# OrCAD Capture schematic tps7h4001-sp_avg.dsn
size B
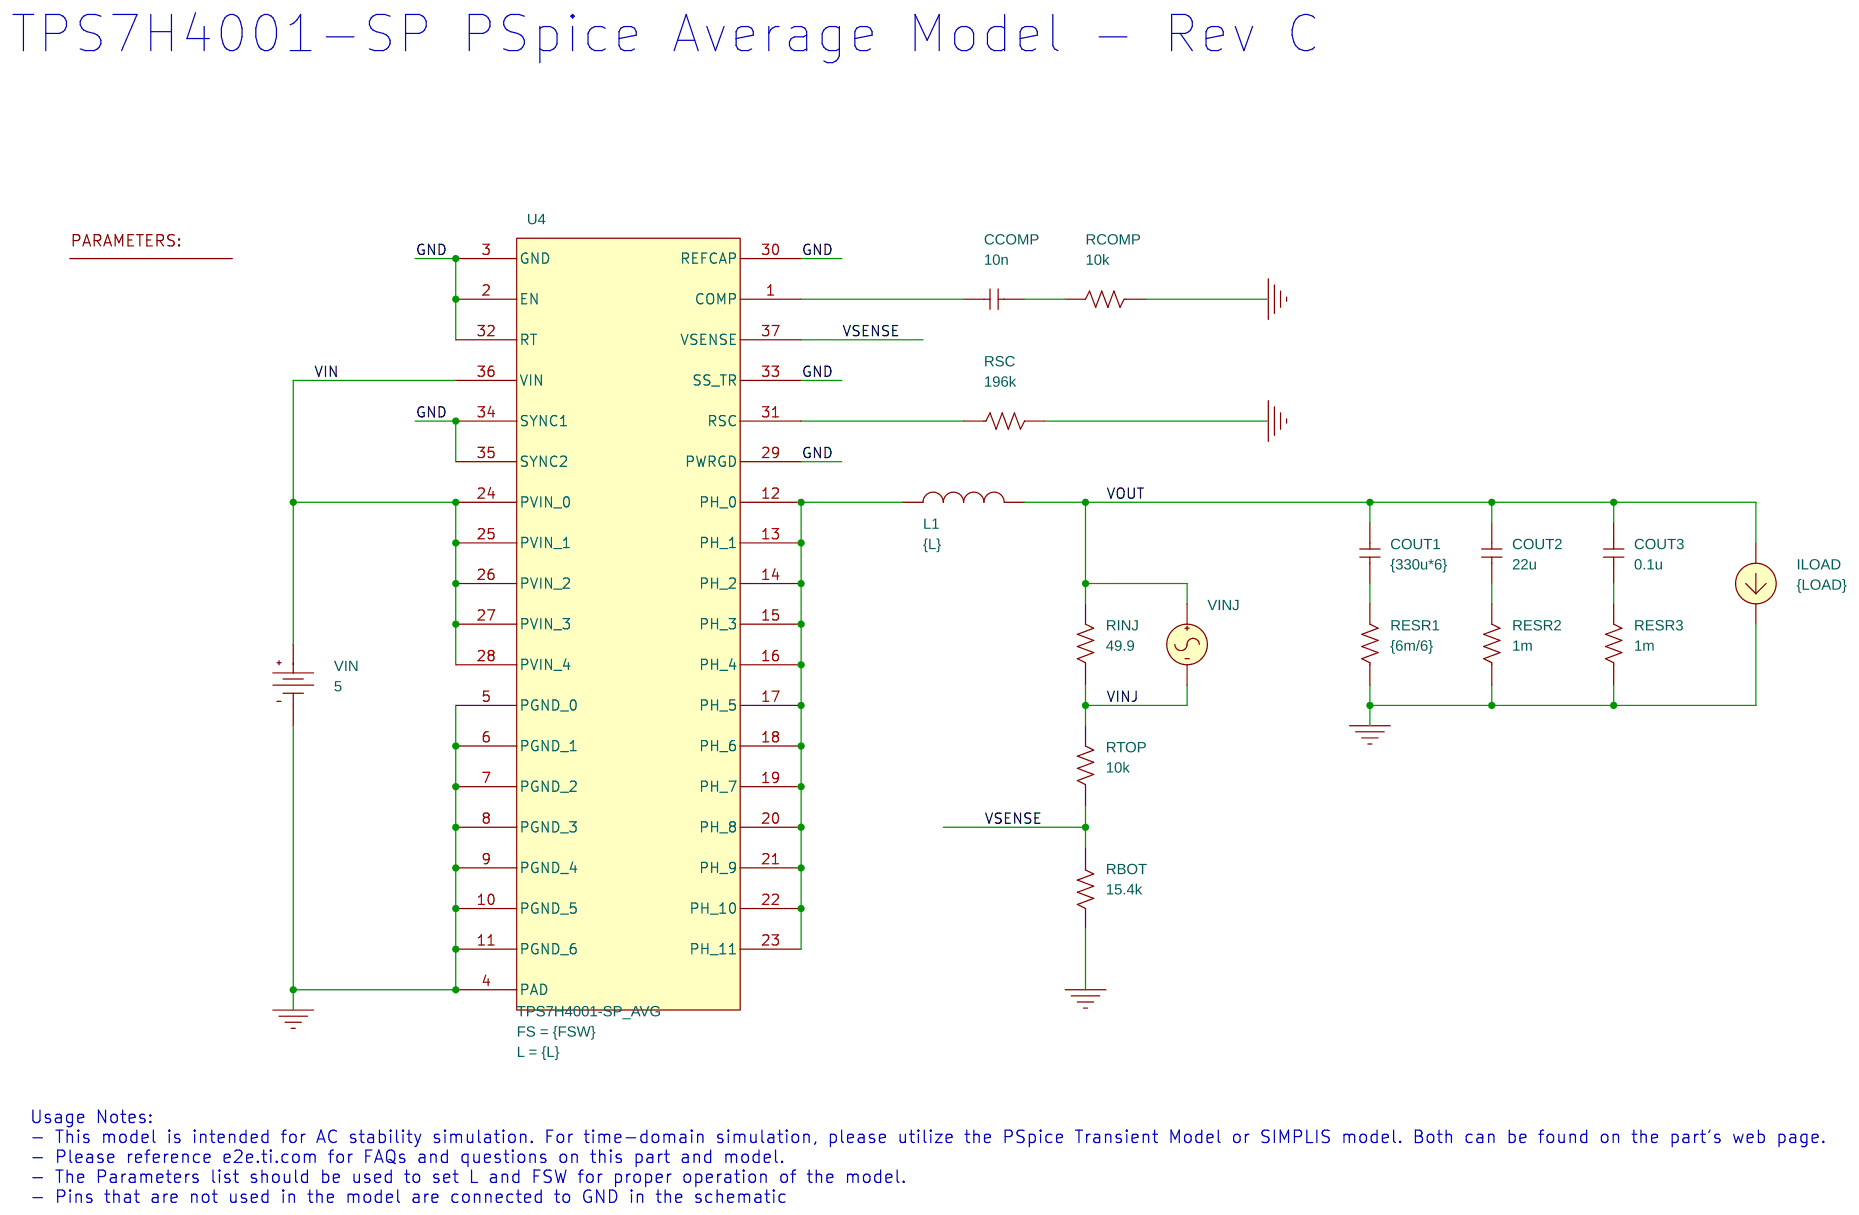
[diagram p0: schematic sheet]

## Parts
1  PARAM
CCOMP  10n  [RAD/CK05]
COUT1  {330u*6}  [RAD/CK05]
COUT2  22u  [RAD/CK05]
COUT3  0.1u  [RAD/CK05]
ILOAD  IDC
L1  {L}  [DISC/.350x.175/LS.200x.100/.034]
RBOT  15.4k  [AX/RC05]
RCOMP  10k  [AX/RC05]
RESR1  {6m/6}  [AX/RC05]
RESR2  1m  [AX/RC05]
RESR3  1m  [AX/RC05]
RINJ  49.9  [AX/RC05]
RSC  196k  [AX/RC05]
RTOP  10k  [AX/RC05]
U4  TPS7H4001-SP_AVG
VIN  VDC
VINJ  VAC

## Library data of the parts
1 = PARAM: FSW: 500k; L: 0.9u; LOAD: 12
CCOMP COUT1-COUT3 = C
ILOAD = IDC: DC: {LOAD}
L1 = L_v2
RBOT RCOMP RESR1-RESR3 RINJ RSC RTOP = R
U4 = TPS7H4001-SP_AVG: FS: {FSW}; L: {L}
VIN = VDC: DC: 5
VINJ = VAC

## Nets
GND: U4.2(EN) U4.3(GND) U4.29(PWRGD) U4.30(REFCAP) U4.32(RT) U4.33(SS_TR) U4.34(SYNC1) U4.35(SYNC2)
VIN: U4.24(PVIN_0) U4.25(PVIN_1) U4.26(PVIN_2) U4.27(PVIN_3) U4.28(PVIN_4) U4.36(VIN) VIN.0(+)
VINJ: RINJ.1 RTOP.2 VINJ.2(-)
0: ILOAD.2(-) RBOT.2 RCOMP.1 RESR1.1 RESR2.1 RESR3.1 RSC.2 U4.4(PAD) U4.5(PGND_0) U4.6(PGND_1) U4.7(PGND_2) U4.8(PGND_3) U4.9(PGND_4) U4.10(PGND_5) U4.11(PGND_6) VIN.1(-)
VOUT: COUT1.1 COUT2.1 COUT3.1 ILOAD.1(+) L1.2 RINJ.2 VINJ.1(+)
VSENSE: RBOT.1 RTOP.1 U4.37(VSENSE)
N16777389: L1.1 U4.12(PH_0) U4.13(PH_1) U4.14(PH_2) U4.15(PH_3) U4.16(PH_4) U4.17(PH_5) U4.18(PH_6) U4.19(PH_7) U4.20(PH_8) U4.21(PH_9) U4.22(PH_10) U4.23(PH_11)
N16777578: COUT2.2 RESR2.2
N16777581: COUT3.2 RESR3.2
N16784509: CCOMP.2 RCOMP.2
N16784525: CCOMP.1 U4.1(COMP)
N16785475: RSC.1 U4.31(RSC)
N16793618: COUT1.2 RESR1.2

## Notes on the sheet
- TPS7H4001-SP PSpice Average Model - Rev C
- Usage Notes:
  - This model is intended for AC stability simulation. For time-domain simulation, please utilize the PSpice Transient Model or SIMPLIS model. Both can be found on the part's web page.
  - Please reference e2e.ti.com for FAQs and questions on this part and model.
  - The Parameters list should be used to set L and FSW for proper operation of the model.
  - Pins that are not used in the model are connected to GND in the schematic
